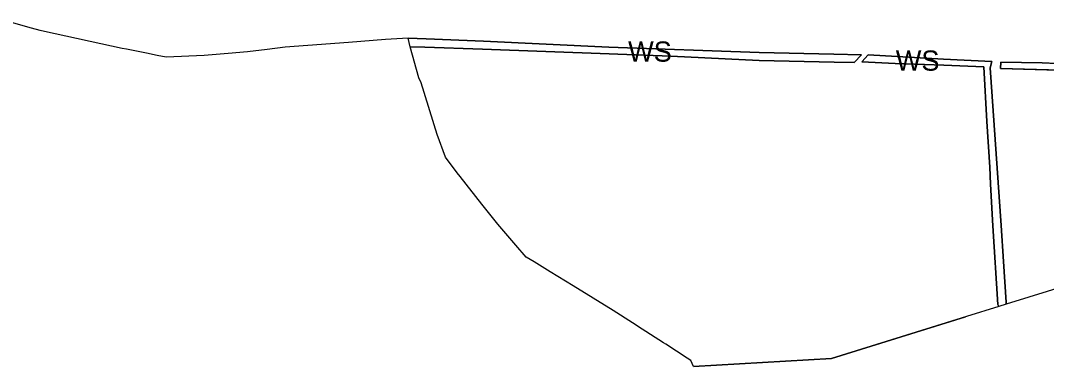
# Model space of a CAD drawing. Extents: x 7417187 to 7419415, y 5539178 to 5540826.
# Drawn here: x 7418229 to 7418735, y 5539178 to 5539349 of the extents above; entities that cross this region are included whole.
import ezdxf

# ---------------------------------------------------------------- set-up
doc = ezdxf.new("R2010")
doc.units = 0
doc.layers.add('linie_rozgraniczajace', color=7, linetype='Continuous')
doc.layers.add('oznaczenia_przeznaczen', color=7, linetype='Continuous')

msp = doc.modelspace()

# ---------------------------------------------------------------- linework, layer by layer
at = {"layer": 'linie_rozgraniczajace'}
for p, q in [((7418234.1, 5539345.03), (7418220.7, 5539348.79)), ((7418238.38, 5539343.83), (7418234.1, 5539345.03)), ((7418240.49, 5539343.37), (7418238.38, 5539343.83)), ((7418278.87, 5539335.02), (7418240.49, 5539343.37)), ((7418390.42, 5539337.96), (7418370.37, 5539336.49)), ((7418408.74, 5539339.45), (7418390.42, 5539337.96)), ((7418419.84, 5539340.12), (7418408.74, 5539339.45)), ((7418420.81, 5539335.73), (7418419.84, 5539340.12)), ((7418419.84, 5539340.12), (7418428.8, 5539339.76)), ((7418428.8, 5539339.76), (7418419.84, 5539340.12)), ((7418428.8, 5539339.76), (7418456.95, 5539338.6)), ((7418456.95, 5539338.6), (7418428.8, 5539339.76)), ((7418456.95, 5539338.6), (7418518.77, 5539335.6)), ((7418518.77, 5539335.6), (7418456.95, 5539338.6)), ((7418280.85, 5539334.59), (7418278.87, 5539335.02)), ((7418290.73, 5539332.63), (7418280.85, 5539334.59)), ((7418296.03, 5539331.47), (7418290.73, 5539332.63)), ((7418331.01, 5539332.51), (7418319.28, 5539331.58)), ((7418340.55, 5539333.27), (7418331.01, 5539332.51)), ((7418350.29, 5539334.53), (7418340.55, 5539333.27)), ((7418359.12, 5539335.67), (7418350.29, 5539334.53)), ((7418370.37, 5539336.49), (7418359.12, 5539335.67)), ((7418428, 5539335.63), (7418420.81, 5539335.73)), ((7418425.05, 5539320.54), (7418420.81, 5539335.73)), ((7418420.81, 5539335.73), (7418428, 5539335.63)), ((7418456.44, 5539334.72), (7418428, 5539335.63)), ((7418428, 5539335.63), (7418456.44, 5539334.72)), ((7418518.9, 5539332.41), (7418456.44, 5539334.72)), ((7418456.44, 5539334.72), (7418518.9, 5539332.41)), ((7418518.77, 5539335.6), (7418593, 5539333.02)), ((7418593, 5539333.02), (7418518.77, 5539335.6)), ((7418549.38, 5539331.11), (7418518.9, 5539332.41)), ((7418518.9, 5539332.41), (7418549.38, 5539331.11)), ((7418593, 5539333.02), (7418629.7, 5539332.21)), ((7418629.7, 5539332.21), (7418593, 5539333.02)), ((7418300.55, 5539330.71), (7418296.03, 5539331.47)), ((7418319.28, 5539331.58), (7418300.55, 5539330.71)), ((7418592.98, 5539329.06), (7418549.38, 5539331.11)), ((7418549.38, 5539331.11), (7418592.98, 5539329.06)), ((7418629.92, 5539328.27), (7418592.98, 5539329.06)), ((7418592.98, 5539329.06), (7418629.92, 5539328.27)), ((7418629.7, 5539332.21), (7418643.5, 5539331.9)), ((7418643.5, 5539331.9), (7418629.7, 5539332.21)), ((7418639.75, 5539328.05), (7418629.92, 5539328.27)), ((7418629.92, 5539328.27), (7418639.75, 5539328.05)), ((7418643.5, 5539331.9), (7418639.75, 5539328.05)), ((7418639.75, 5539328.05), (7418643.5, 5539331.9)), ((7418643.65, 5539328.34), (7418646.73, 5539331.79)), ((7418646.73, 5539331.79), (7418643.65, 5539328.34)), ((7418660, 5539327.6), (7418643.65, 5539328.34)), ((7418643.65, 5539328.34), (7418660, 5539327.6)), ((7418646.73, 5539331.79), (7418683.92, 5539329.71)), ((7418683.92, 5539329.71), (7418646.73, 5539331.79)), ((7418684.02, 5539326.77), (7418660, 5539327.6)), ((7418660, 5539327.6), (7418684.02, 5539326.77)), ((7418683.92, 5539329.71), (7418707.69, 5539328.53)), ((7418707.69, 5539328.53), (7418683.92, 5539329.71)), ((7418707.69, 5539328.53), (7418706.86, 5539325.46)), ((7418706.86, 5539325.46), (7418707.69, 5539328.53)), ((7418712.13, 5539328.28), (7418711.99, 5539325.17)), ((7418732.47, 5539327.88), (7418712.13, 5539328.28)), ((7418747.27, 5539327.17), (7418732.47, 5539327.88)), ((7418703.73, 5539325.89), (7418684.02, 5539326.77)), ((7418684.02, 5539326.77), (7418703.73, 5539325.89)), ((7418705.23, 5539299.01), (7418703.73, 5539325.89)), ((7418703.73, 5539325.89), (7418705.23, 5539299.01)), ((7418706.86, 5539325.46), (7418712.24, 5539247.62)), ((7418712.24, 5539247.62), (7418706.86, 5539325.46)), ((7418711.99, 5539325.17), (7418747.48, 5539324.11)), ((7418426.25, 5539318.04), (7418425.05, 5539320.54)), ((7418434.2, 5539292.52), (7418426.25, 5539318.04)), ((7418706.73, 5539276.36), (7418705.23, 5539299.01)), ((7418705.23, 5539299.01), (7418706.73, 5539276.36)), ((7418438.27, 5539281.38), (7418434.2, 5539292.52)), ((7418444.04, 5539273.55), (7418438.27, 5539281.38)), ((7418445.45, 5539271.75), (7418444.04, 5539273.55)), ((7418456.2, 5539258.04), (7418445.45, 5539271.75)), ((7418706.97, 5539267.92), (7418706.73, 5539276.36)), ((7418706.73, 5539276.36), (7418706.97, 5539267.92)), ((7418708.12, 5539247.45), (7418706.97, 5539267.92)), ((7418706.97, 5539267.92), (7418708.12, 5539247.45)), ((7418464.06, 5539248.19), (7418456.2, 5539258.04)), ((7418472.99, 5539237.91), (7418464.06, 5539248.19)), ((7418710.61, 5539208.57), (7418708.12, 5539247.45)), ((7418708.12, 5539247.45), (7418710.61, 5539208.57)), ((7418712.24, 5539247.62), (7418713.47, 5539229.88)), ((7418713.47, 5539229.88), (7418712.24, 5539247.62)), ((7418478.1, 5539232.03), (7418472.99, 5539237.91)), ((7418481.94, 5539229.63), (7418478.1, 5539232.03)), ((7418489.82, 5539224.7), (7418481.94, 5539229.63)), ((7418713.47, 5539229.88), (7418714.82, 5539209.82)), ((7418714.82, 5539209.82), (7418713.47, 5539229.88)), ((7418501.16, 5539217.88), (7418489.82, 5539224.7)), ((7418520.93, 5539205.65), (7418501.16, 5539217.88)), ((7418749.84, 5539219.63), (7418714.84, 5539208.73)), ((7418711.12, 5539207.57), (7418695.24, 5539202.62)), ((7418711.12, 5539207.57), (7418710.61, 5539208.57)), ((7418710.61, 5539208.57), (7418711.12, 5539207.57)), ((7418714.84, 5539208.73), (7418711.12, 5539207.57)), ((7418714.82, 5539209.82), (7418714.84, 5539208.73)), ((7418714.84, 5539208.73), (7418714.82, 5539209.82)), ((7418530.47, 5539199.51), (7418520.93, 5539205.65)), ((7418695.24, 5539202.62), (7418628.59, 5539181.85)), ((7418694.71, 5539202.45), (7418628.59, 5539181.85)), ((7418628.59, 5539181.85), (7418694.71, 5539202.45)), ((7418530.78, 5539199.31), (7418530.47, 5539199.51)), ((7418532.96, 5539197.91), (7418530.78, 5539199.31)), ((7418545.82, 5539189.62), (7418532.96, 5539197.91)), ((7418546.89, 5539188.93), (7418545.82, 5539189.62)), ((7418557.46, 5539182.16), (7418546.89, 5539188.93)), ((7418559.26, 5539181.01), (7418557.46, 5539182.16)), ((7418560.64, 5539177.98), (7418559.26, 5539181.01)), ((7418628.59, 5539181.85), (7418560.64, 5539177.98)), ((7418628.59, 5539181.85), (7418560.64, 5539177.98)), ((7418560.64, 5539177.98), (7418628.59, 5539181.85)), ((7418560.64, 5539177.98), (7418560.64, 5539177.98)), ((7418560.64, 5539177.98), (7418560.64, 5539177.98))]:
    msp.add_line(p, q, dxfattribs=at)
msp.add_lwpolyline([(7418827.95, 5539323.88), (7418826.63, 5539322.55), (7418800.43, 5539322.92), (7418775.99, 5539323.33), (7418747.48, 5539324.11), (7418711.99, 5539325.17), (7418712.13, 5539328.28), (7418732.47, 5539327.88), (7418747.27, 5539327.17), (7418775.95, 5539326.17), (7418799.51, 5539325.47), (7418827.14, 5539324.77)], close=True, dxfattribs=at)

# ---------------------------------------------------------------- texts
at = {"layer": 'oznaczenia_przeznaczen'}
for p in [(7418528.32, 5539328.45), (7418660.33, 5539324)]:
    msp.add_text('WS', height=10, dxfattribs=at).set_placement(p)

doc.saveas('drawing.dxf')
